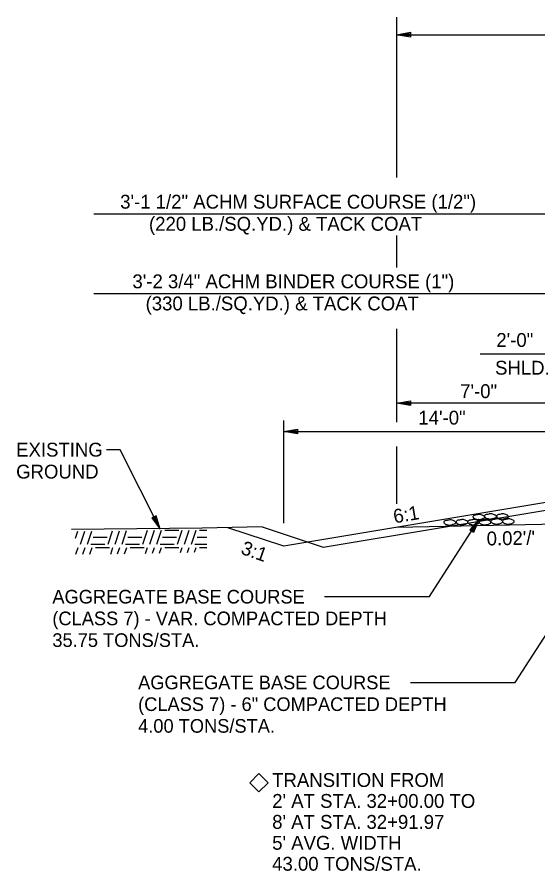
# Model space of a CAD drawing. Extents: x 1461570 to 1461697, y 1686711 to 1686957.
# Drawn here: x 1461570.2 to 1461592.73, y 1686770.47 to 1686807.42 of the extents above; entities that cross this region are included whole.
import ezdxf

# ---------------------------------------------------------------- set-up
doc = ezdxf.new("R2010")
doc.units = 0
for name, color, linetype in [('1', 7, 'Continuous'), ('10', 7, 'Continuous'), ('19', 7, 'Continuous'), ('20', 7, 'Continuous'), ('42', 7, 'Continuous'), ('Default', 7, 'Continuous'), ('Level 9', 7, 'Continuous'), ('R_Draft', 7, 'Continuous')]:
    doc.layers.add(name, color=color, linetype=linetype)

# ---------------------------------------------------------------- blocks, each defined once
blk = doc.blocks.new('ROCKS')
at = {"layer": '1'}
blk.add_spline([(0.013, 0.06), (0.053, 0.053), (0.107, 0.033), (0.133, 0.013), (0.133, -0.007), (0.12, -0.033), (0.107, -0.04), (0.073, -0.053), (0.033, -0.067), (0.013, -0.067), (-0.02, -0.06), (-0.06, -0.053), (-0.087, -0.047), (-0.113, -0.02), (-0.113, -0.007), (-0.107, 0.02), (-0.087, 0.033), (-0.067, 0.047), (-0.033, 0.053), (-0.02, 0.06), (0.013, 0.06)], degree=3, dxfattribs=at)

msp = doc.modelspace()

# ---------------------------------------------------------------- linework, layer by layer
at = {"layer": '10'}
msp.add_lwpolyline([(1461580.666, 1686774.684), (1461581.064, 1686774.287), (1461580.666, 1686773.889), (1461580.269, 1686774.287)], close=True, dxfattribs=at)
at = {"layer": '19'}
for p, q in [((1461586.622, 1686790.71), (1461587.222, 1686790.815)), ((1461587.222, 1686790.605), (1461586.622, 1686790.71)), ((1461586.782, 1686790.725), (1461587.222, 1686790.76)), ((1461587.222, 1686790.655), (1461586.782, 1686790.695)), ((1461587.222, 1686790.815), (1461587.222, 1686790.605)), ((1461593.738, 1686786.521), (1461581.738, 1686784.521)), ((1461588.042, 1686782.342), (1461590.19, 1686785.689)), ((1461590.19, 1686785.689), (1461589.782, 1686785.237)), ((1461589.959, 1686785.127), (1461590.19, 1686785.689)), ((1461591.75, 1686778.631), (1461596.349, 1686785.793)), ((1461581.738, 1686784.521), (1461579.324, 1686785.325)), ((1461596.654, 1686785.535), (1461586.622, 1686785.335)), ((1461590.095, 1686785.56), (1461589.828, 1686785.211)), ((1461589.918, 1686785.154), (1461590.119, 1686785.545)), ((1461589.782, 1686785.237), (1461589.959, 1686785.127)), ((1461583.506, 1686782.342), (1461588.042, 1686782.342)), ((1461587.215, 1686778.631), (1461591.75, 1686778.631))]:
    msp.add_line(p, q, dxfattribs=at)
at = {"layer": '20'}
for p, q in [((1461586.622, 1686800.472), (1461586.622, 1686807.418)), ((1461586.617, 1686806.656), (1461587.217, 1686806.761)), ((1461587.217, 1686806.761), (1461587.217, 1686806.551)), ((1461587.217, 1686806.551), (1461586.617, 1686806.656)), ((1461586.622, 1686806.655), (1461626.853, 1686806.655)), ((1461586.777, 1686806.671), (1461587.217, 1686806.706)), ((1461587.217, 1686806.601), (1461586.777, 1686806.641)), ((1461593.611, 1686798.892), (1461573.526, 1686798.892)), ((1461586.622, 1686796.588), (1461586.622, 1686797.968)), ((1461593.501, 1686795.446), (1461573.523, 1686795.446)), ((1461586.622, 1686789.893), (1461586.622, 1686793.93)), ((1461581.738, 1686785.522), (1461581.738, 1686789.958)), ((1461581.738, 1686789.485), (1461582.338, 1686789.59)), ((1461582.338, 1686789.38), (1461581.738, 1686789.485)), ((1461581.898, 1686789.5), (1461582.338, 1686789.535)), ((1461582.338, 1686789.43), (1461581.898, 1686789.47)), ((1461582.338, 1686789.59), (1461582.338, 1686789.38)), ((1461586.622, 1686786.355), (1461586.622, 1686788.836)), ((1461576.223, 1686785.844), (1461576.036, 1686785.75)), ((1461576.036, 1686785.75), (1461576.399, 1686785.261)), ((1461576.08, 1686785.772), (1461576.314, 1686785.397)), ((1461576.341, 1686785.411), (1461576.174, 1686785.819)), ((1461576.399, 1686785.261), (1461576.223, 1686785.844))]:
    msp.add_line(p, q, dxfattribs=at)
msp.add_lwpolyline([(1461576.399, 1686785.261), (1461574.669, 1686788.7), (1461574.069, 1686788.7)], dxfattribs=at)
at = {"layer": '42'}
for p, q in [((1461590.233, 1686792.846), (1461594.743, 1686792.846)), ((1461581.738, 1686789.485), (1461595.738, 1686789.485)), ((1461572.732, 1686784.873), (1461572.834, 1686785.179)), ((1461572.945, 1686784.612), (1461573.133, 1686785.176)), ((1461573.245, 1686784.612), (1461573.432, 1686785.174)), ((1461574.145, 1686784.612), (1461574.336, 1686785.184)), ((1461574.445, 1686784.612), (1461574.638, 1686785.19)), ((1461574.745, 1686784.612), (1461574.94, 1686785.196)), ((1461575.645, 1686784.612), (1461575.845, 1686785.212)), ((1461575.945, 1686784.612), (1461576.145, 1686785.212)), ((1461576.245, 1686784.612), (1461576.445, 1686785.212)), ((1461576.595, 1686785.212), (1461577.195, 1686785.212)), ((1461577.145, 1686784.612), (1461577.345, 1686785.212)), ((1461577.445, 1686784.612), (1461577.645, 1686785.212)), ((1461577.745, 1686784.612), (1461577.945, 1686785.212)), ((1461578.095, 1686785.212), (1461578.405, 1686785.212)), ((1461573.395, 1686784.612), (1461573.995, 1686784.612)), ((1461573.495, 1686784.912), (1461574.095, 1686784.912)), ((1461574.895, 1686784.612), (1461575.495, 1686784.612)), ((1461574.995, 1686784.912), (1461575.595, 1686784.912)), ((1461576.395, 1686784.612), (1461576.995, 1686784.612)), ((1461576.495, 1686784.912), (1461577.095, 1686784.912)), ((1461577.895, 1686784.612), (1461578.405, 1686784.612)), ((1461577.995, 1686784.912), (1461578.405, 1686784.912)), ((1461572.751, 1686784.179), (1461572.845, 1686784.462)), ((1461573.05, 1686784.177), (1461573.145, 1686784.462)), ((1461573.349, 1686784.175), (1461573.445, 1686784.462)), ((1461573.595, 1686784.462), (1461574.195, 1686784.462)), ((1461574.252, 1686784.182), (1461574.345, 1686784.462)), ((1461574.554, 1686784.188), (1461574.645, 1686784.462)), ((1461574.856, 1686784.195), (1461574.945, 1686784.462)), ((1461575.095, 1686784.462), (1461575.645, 1686784.462)), ((1461575.645, 1686784.462), (1461575.695, 1686784.462)), ((1461575.762, 1686784.213), (1461575.845, 1686784.462)), ((1461576.064, 1686784.22), (1461576.145, 1686784.462)), ((1461576.366, 1686784.226), (1461576.445, 1686784.462)), ((1461576.595, 1686784.462), (1461577.195, 1686784.462)), ((1461577.272, 1686784.245), (1461577.345, 1686784.462)), ((1461577.576, 1686784.255), (1461577.645, 1686784.462)), ((1461577.882, 1686784.272), (1461577.945, 1686784.462)), ((1461578.095, 1686784.462), (1461578.405, 1686784.462))]:
    msp.add_line(p, q, dxfattribs=at)
at = {"layer": 'Level 9'}
msp.add_line((1461593.738, 1686790.71), (1461586.622, 1686790.71), dxfattribs=at)
at = {"layer": 'R_Draft'}
for p, q in [((1461583.437, 1686784.478), (1461595.238, 1686786.445)), ((1461580.804, 1686785.356), (1461583.437, 1686784.478))]:
    msp.add_line(p, q, dxfattribs=at)
msp.add_lwpolyline([(1461580.804, 1686785.356), (1461578.206, 1686785.302), (1461572.562, 1686785.245)], dxfattribs=at)

# ---------------------------------------------------------------- block references
at = {"layer": '1', "xscale": 1.968733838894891, "yscale": -1.968733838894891}
for p in [(1461589.424, 1686785.557), (1461589.922, 1686785.557), (1461590.156, 1686785.78), (1461590.418, 1686785.557), (1461590.654, 1686785.806), (1461590.93, 1686785.583), (1461591.179, 1686785.806), (1461591.429, 1686785.583), (1461588.899, 1686785.544)]:
    msp.add_blockref('ROCKS', p, dxfattribs=at)

# ---------------------------------------------------------------- texts
at = {"layer": '10'}
for s, p in [('EXISTING', (1461570.164, 1686788.4)), ('GROUND', (1461570.164, 1686787.45))]:
    msp.add_text(s, height=0.6, dxfattribs=at).set_placement(p)
at = {"layer": '19'}
for s, height, rotation, p in [('2\'-0"', 0.6, 360, (1461590.93, 1686793.146)), ('SHLD.', 0.6, 360, (1461590.875, 1686791.946)), ('14\'-0"', 0.6, 360, (1461587.559, 1686789.785)), ('6:1', 0.6, 9.8416, (1461586.528, 1686785.509)), ("0.02'/'", 0.6, 1.1458, (1461590.518, 1686784.553)), ('3:1', 0.6, 340.4943, (1461579.844, 1686784.206)), ('AGGREGATE BASE COURSE', 0.59001, 360, (1461571.73, 1686782.044)), ('(CLASS 7) - VAR. COMPACTED DEPTH', 0.59001, 360, (1461571.73, 1686781.104)), ('35.75 TONS/STA.', 0.59001, 360, (1461571.73, 1686780.164)), ('AGGREGATE BASE COURSE', 0.59001, 360, (1461575.439, 1686778.333)), ('(CLASS 7) - 6" COMPACTED DEPTH', 0.59001, 360, (1461575.439, 1686777.393)), ('4.00 TONS/STA.', 0.59001, 360, (1461575.439, 1686776.453)), ('TRANSITION FROM', 0.6, 359.9954, (1461581.237, 1686774.107)), ("2' AT STA. 32+00.00 TO", 0.6, 359.9954, (1461581.237, 1686773.201)), ("8' AT STA. 32+91.97", 0.6, 359.9954, (1461581.237, 1686772.294)), ("5' AVG. WIDTH", 0.6, 359.9954, (1461581.236, 1686771.388)), ('43.00 TONS/STA.', 0.6, 359.9954, (1461581.236, 1686770.482))]:
    msp.add_text(s, height=height, rotation=rotation, dxfattribs=at).set_placement(p)
msp.add_text('7\'-0"', height=0.6, dxfattribs=at).set_placement((1461589.366, 1686790.932))
at = {"layer": 'Default'}
for s, p in [('3\'-1 1/2" ACHM SURFACE COURSE (1/2")', (1461574.664, 1686799.129)), ('(220 LB./SQ.YD.) & TACK COAT', (1461575.909, 1686798.173)), ('3\'-2 3/4" ACHM BINDER COURSE (1")', (1461575.193, 1686795.683)), ('(330 LB./SQ.YD.) & TACK COAT', (1461575.763, 1686794.727))]:
    msp.add_text(s, height=0.60001, dxfattribs=at).set_placement(p)

doc.saveas('drawing.dxf')
